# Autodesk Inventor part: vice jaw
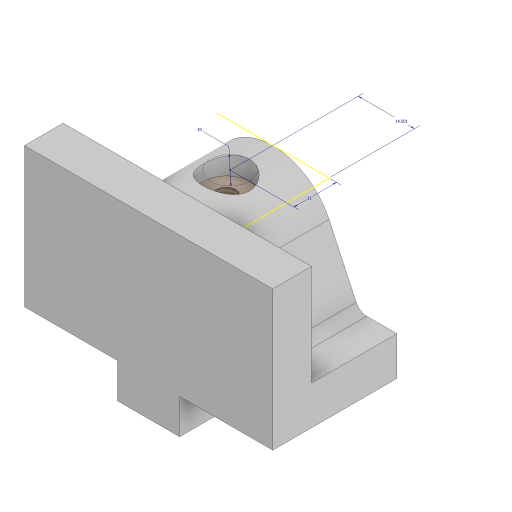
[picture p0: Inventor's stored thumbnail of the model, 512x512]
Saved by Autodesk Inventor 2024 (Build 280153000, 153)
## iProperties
Created: 2016-03
Part Number: vice jaw
Material: Generic
Document SubType Name: Modeling
Designer: Sandeep
Density: 1 g/cm^3
Appearance: Default
Mass: 55.5986 g
Surface Area: 129.526 cm^2
Volume: 55.5986 cm^3
Author: Sandeep
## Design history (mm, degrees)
sketch "Sketch1"
  geometry: L1 (0, 0)-(-32, 0); L2 (-32, 0)-(-32, 36); L3 (-32, 36)-(-22, 36); L4 (-22, 36)-(-22, 10); L5 (-22, 10)-(0, 10); L6 (0, 10)-(0, 0)
  constraints: 12 end point, 5 perpendicular, 1 horizontal
  dimensions: "d0" = 36 distance between parallel lines of L1 L3; "d1" = 32 distance of L1.start L1.end; "d2" = 10 distance of L5.end L1.start; "d3" = 10 distance of L2.end L3.end
extrude "Extrusion1" new body sketch "Sketch1" stored distance "d4" = 64; taper "d5" = 0 deg
sketch "Sketch2"
  geometry: L1 (64, 10)-(64, 0) reference; L2 (64, 10)-(64, 0); L3 (64, 0)-(54.317, 0); L4 (64, 0)-(0, 0) reference; L5 (54.317, 0)-(46.501, -16.762); L6 (0, 0)-(0, 10); L7 (0, 10)-(64, 10); L8 (64, -26)-(0, -26) reference; L9 (0, 0)-(9.683, 0); L10 (32, 10)-(32, -39.451); L11 (9.683, 0)-(17.499, -16.762); A1 r 16 centre (32, -10) between (17.499, -16.762) and (46.501, -16.762); 1 further point
  constraints: 16 end point, 3 point on line, 2 collinear, 2 perpendicular, 2 point on circle, 2 symmetric about line, 2 tangent, 1 centre point, 1 coincident, 1 vertical
  dimensions: "d8" = 16 radius of A1; "d9" = 50 deg angle of L11 L5
extrude "Extrusion2" join sketch "Sketch2" stored distance "d10" = 32; taper "d11" = 0 deg
fillet "Fillet1" dims "d12" = 3
sketch "Sketch3"
  geometry: L1 (40, 0)-(40, 9); L2 (40, 9)-(24, 9); L3 (24, 9)-(24, 0); L4 (24, 0)-(40, 0); L5 (0, 0)-(64, 0) reference; L6 (32, 0)-(32, -54.171)
  constraints: 10 end point, 2 perpendicular, 2 vertical, 1 collinear, 1 point on line, 1 other
  dimensions: "d13" = 16 distance between parallel lines of L3 L1; "d14" = 9 distance of L2.end L3.end
extrude "Extrusion3" join sketch "Sketch3" stored distance "d15" = 32; taper "d16" = 0 deg
sketch "Sketch4"
  geometry: L1 (-24, 19)-(-40, 19) reference; L2 (-32, 19)-(-32, -29.453); C1 r 6 at (-32, -10); A1 r 16 centre (-32, -10) between (-46.501, -16.762) and (-17.499, -16.762) reference; 1 further point
  constraints: 2 end point, 1 centre point, 1 concentric, 1 midpoint, 1 point on line, 1 vertical
  dimensions: "d17" = 12 diameter of C1
extrude "Extrusion4" cut sketch "Sketch4" distance "d18" = 24; taper "d19" = 0 deg
workplane "Work Plane1"
workplane "Work Plane2"
hole "Hole1" diameter "d37" = 4.917; stored, may be unused: countersink angle "d41" = 90 deg, drill point angle "d43" = 118 deg; dims "d35" = 8, "d36" = 8, "d38" = 12, "d39" = 4, "d40" = 2, "d42" = 16
hole "Hole2" diameter "d46" = 4.917; stored, may be unused: countersink angle "d50" = 90 deg, drill point angle "d52" = 118 deg; dims "d44" = 8, "d45" = 8, "d47" = 12, "d48" = 4, "d49" = 2, "d51" = 16
hole "Hole3" diameter "d55" = 4.917; stored, may be unused: countersink angle "d59" = 82 deg, drill point angle "d61" = 118 deg; dims "d53" = 20, "d54" = 32, "d56" = 12, "d57" = 12, "d58" = 5, "d60" = 17.1
body "Solid1"
sketch "Sketch6"
  geometry: 1 further point
sketch "Sketch7"
  geometry: L1 (14.501, 0)-(-14.501, 0) reference; L2 (14.501, 0)-(14.501, -22) reference; C1 r 5 at (0, -11); 1 further point
  constraints: 1 centre point
  dimensions: "d22" = 10 diameter of C1; "d23" = 11 distance from line of L1 C1.centre; "d24" = 14.50092 distance from line of C1.centre L2
sketch "Sketch10"
  geometry: 1 further point
